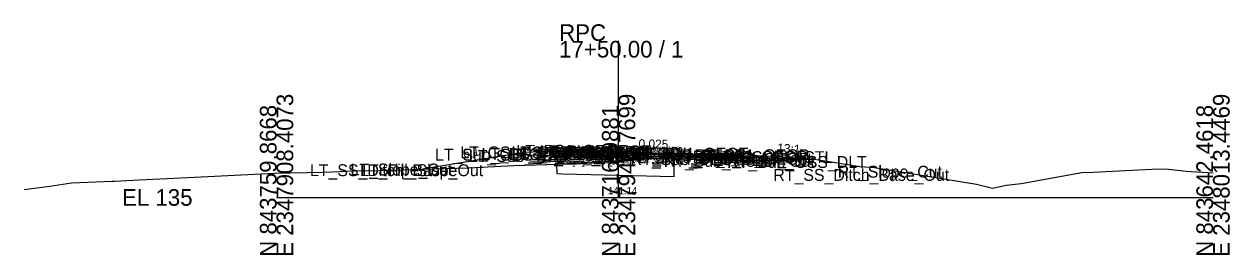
# Model space of a CAD drawing. Extents: x -26 to 203, y -10 to 7538.
# Drawn here: x 0 to 202.8, y 3990.3 to 4029.2 of the extents above; entities that cross this region are included whole.
import ezdxf

# ---------------------------------------------------------------- set-up
doc = ezdxf.new("R2010")
doc.units = 0
for name, color, linetype in [('Default', 7, 'Continuous'), ('Exist Cross Section Cell', 7, 'Continuous'), ('Exist XS Center Line Elevation Label', 7, 'Continuous'), ('Exist XS Ground Line', 7, 'Continuous'), ('Prop CMT Pvmt Course 1', 7, 'Continuous'), ('Prop CMT Pvmt Course 2', 7, 'Continuous'), ('Prop CMT Pvmt Course 3', 7, 'Continuous'), ('Prop CMT Pvmt Surface', 7, 'Continuous'), ('Prop CMT Pvmt Surface Shoulder', 7, 'Continuous'), ('Prop CMT Shld Paved Course 1', 7, 'Continuous'), ('Prop CMT Shld Paved Course 2', 7, 'Continuous'), ('Prop CMT Shld Paved Course 3', 7, 'Continuous'), ('Prop CMT Slope Grass', 7, 'Continuous'), ('Prop CMT Subgrade Earthwork', 7, 'Continuous'), ('Prop Road Sect_ Recs - UC (Outline)', 7, 'Continuous'), ('Prop XS Earthwork Shape', 7, 'Continuous'), ('Prop XS SE Text', 7, 'Continuous'), ('Prop XS Side Slope Text', 7, 'Continuous'), ('Scratch_Level_0', 7, 'Continuous')]:
    doc.layers.add(name, color=color, linetype=linetype)

msp = doc.modelspace()

# ---------------------------------------------------------------- linework, layer by layer
at = {"layer": 'Exist Cross Section Cell'}
for p, q in [((100, 4000), (100, 4026.39)), ((42.46, 4000), (100, 4000)), ((100, 4000), (200, 4000))]:
    msp.add_line(p, q, dxfattribs=at)
at = {"layer": 'Exist XS Ground Line'}
msp.add_lwpolyline([(0, 4001.35), (4.35, 4001.89), (7.96, 4002.46), (14.79, 4002.74), (15.27, 4002.76), (19.33, 4002.97), (28.68, 4003.44), (29.79, 4003.48), (42.1, 4004.07), (43.37, 4004.13), (44.78, 4004.17), (50.45, 4004.29), (55.52, 4004.46), (59.78, 4004.57), (68.94, 4004.8), (74.78, 4005.02), (82.36, 4005.37), (89.78, 4005.6), (92.94, 4005.67), (98.95, 4006.06), (100, 4006.14), (109.3, 4006.84), (110.35, 4006.89), (111.83, 4006.98), (112.49, 4006.99), (113.07, 4006.99), (113.65, 4006.98), (115.14, 4006.95), (115.87, 4006.94), (116.65, 4006.93), (118.51, 4006.89), (120.39, 4006.85), (121.19, 4006.84), (121.87, 4006.82), (124.18, 4006.76), (125.2, 4006.73), (126.45, 4006.69), (127.88, 4006.65), (128.57, 4006.63), (129.52, 4006.6), (131.75, 4006.5), (132.16, 4006.48), (132.88, 4006.44), (135.82, 4005.98), (140.61, 4005.21), (143.06, 4005.03), (160.23, 4002.25), (162.89, 4001.58), (165.18, 4002.05), (167.73, 4002.37), (177.93, 4004.18), (179.77, 4004.28), (189.71, 4004.77), (192.09, 4004.85), (195.51, 4004.45), (200, 4004.13)], dxfattribs=at)
at = {"layer": 'Prop CMT Pvmt Course 1'}
for p, q in [((100, 4007.67), (96, 4007.77)), ((96, 4007.77), (96, 4007.52)), ((96, 4007.52), (100, 4007.42)), ((100, 4007.42), (100, 4007.67)), ((100, 4007.67), (112, 4007.37)), ((100, 4007.42), (100, 4007.67)), ((100, 4007.42), (100, 4007.54)), ((100, 4007.54), (100, 4007.54)), ((100, 4007.54), (100, 4007.42)), ((100, 4007.42), (100, 4007.54)), ((100, 4007.54), (100, 4007.54)), ((100, 4007.54), (100, 4007.42)), ((100, 4007.42), (100, 4007.42)), ((112, 4007.12), (100, 4007.42)), ((100, 4007.42), (100, 4007.42)), ((112, 4007.37), (112, 4007.12))]:
    msp.add_line(p, q, dxfattribs=at)
at = {"layer": 'Prop CMT Pvmt Course 2'}
for p, q in [((100, 4007.42), (96, 4007.52)), ((96, 4007.52), (96, 4007.18)), ((96, 4007.18), (100, 4007.08)), ((100, 4007.08), (100, 4007.42)), ((100, 4007.08), (100, 4007.42)), ((100, 4007.42), (112, 4007.12)), ((112, 4006.78), (100, 4007.08)), ((112, 4007.12), (112, 4006.78))]:
    msp.add_line(p, q, dxfattribs=at)
at = {"layer": 'Prop CMT Pvmt Course 3'}
for p, q in [((100, 4007.08), (96, 4007.18)), ((96, 4007.18), (96, 4006.85)), ((96, 4006.85), (100, 4006.75)), ((100, 4006.75), (100, 4007.08)), ((100, 4007.08), (112, 4006.78)), ((100, 4006.75), (100, 4007.08)), ((112, 4006.45), (100, 4006.75)), ((112, 4006.78), (112, 4006.45))]:
    msp.add_line(p, q, dxfattribs=at)
at = {"layer": 'Prop CMT Pvmt Surface'}
for q in [(96, 4007.77), (112, 4007.37)]:
    msp.add_line((100, 4007.67), q, dxfattribs=at)
at = {"layer": 'Prop CMT Pvmt Surface Shoulder'}
for p, q in [((96, 4007.77), (92, 4007.87)), ((112, 4007.37), (122, 4007.12))]:
    msp.add_line(p, q, dxfattribs=at)
at = {"layer": 'Prop CMT Shld Paved Course 1'}
for p, q in [((92, 4007.87), (91.76, 4007.62)), ((91.76, 4007.62), (96, 4007.52)), ((96, 4007.77), (92, 4007.87)), ((96, 4007.52), (96, 4007.77)), ((112, 4007.37), (122, 4007.12)), ((112, 4007.12), (112, 4007.37)), ((122.26, 4006.86), (112, 4007.12)), ((122, 4007.12), (122.26, 4006.86))]:
    msp.add_line(p, q, dxfattribs=at)
at = {"layer": 'Prop CMT Shld Paved Course 2'}
for p, q in [((91.76, 4007.62), (91.43, 4007.3)), ((91.43, 4007.3), (96, 4007.18)), ((96, 4007.52), (91.76, 4007.62)), ((96, 4007.18), (96, 4007.52)), ((112, 4007.12), (122.26, 4006.86)), ((112, 4006.78), (112, 4007.12)), ((122.6, 4006.52), (112, 4006.78)), ((122.26, 4006.86), (122.6, 4006.52))]:
    msp.add_line(p, q, dxfattribs=at)
at = {"layer": 'Prop CMT Shld Paved Course 3'}
for p, q in [((90.93, 4007.31), (90.61, 4006.99)), ((90.61, 4006.99), (96, 4006.85)), ((91.43, 4007.3), (90.93, 4007.31)), ((96, 4007.18), (91.43, 4007.3)), ((96, 4006.85), (96, 4007.18)), ((112, 4006.78), (122.6, 4006.52)), ((112, 4006.45), (112, 4006.78)), ((123.44, 4006.16), (112, 4006.45)), ((122.6, 4006.52), (123.1, 4006.51)), ((123.1, 4006.51), (123.44, 4006.16))]:
    msp.add_line(p, q, dxfattribs=at)
at = {"layer": 'Prop CMT Slope Grass'}
for p, q in [((84, 4007.59), (66.99, 4004.75)), ((92, 4007.87), (84, 4007.59)), ((122, 4007.12), (126, 4006.98)), ((126, 4006.98), (132.88, 4006.44))]:
    msp.add_line(p, q, dxfattribs=at)
at = {"layer": 'Prop CMT Subgrade Earthwork'}
for p, q in [((90.61, 4006.99), (81.72, 4007.21)), ((96, 4006.85), (90.61, 4006.99)), ((100, 4006.75), (96, 4006.85)), ((100, 4006.75), (112, 4006.45)), ((112, 4006.45), (123.44, 4006.16)), ((123.44, 4006.16), (132.88, 4006.44))]:
    msp.add_line(p, q, dxfattribs=at)
at = {"layer": 'Prop Road Sect_ Recs - UC (Outline)'}
msp.add_lwpolyline([(109.34, 4003.52), (109.34, 4003.52), (109.34, 4006.55), (109.34, 4006.55), (109.34, 4006.53), (106, 4006.6), (92.94, 4005.67), (90.57, 4005.62), (89.57, 4005.6), (89.6, 4004.01), (90.61, 4003.99), (100, 4003.75)], close=True, dxfattribs=at)
at = {"layer": 'Prop XS Earthwork Shape'}
for points in [[(100, 4006.14), (106.07, 4006.6), (100, 4006.75), (96, 4006.85), (90.61, 4006.99), (81.72, 4007.21), (66.99, 4004.75), (68.94, 4004.8), (74.78, 4005.02), (82.36, 4005.37), (89.78, 4005.6), (92.94, 4005.67), (98.95, 4006.06)], [(109.3, 4006.84), (110.35, 4006.89), (111.83, 4006.98), (112.49, 4006.99), (113.07, 4006.99), (113.65, 4006.98), (115.14, 4006.95), (115.87, 4006.94), (116.65, 4006.93), (118.51, 4006.89), (120.39, 4006.85), (121.19, 4006.84), (121.87, 4006.82), (124.18, 4006.76), (125.2, 4006.73), (126.45, 4006.69), (127.88, 4006.65), (128.57, 4006.63), (129.52, 4006.6), (131.75, 4006.5), (132.16, 4006.48), (132.88, 4006.44), (123.44, 4006.16), (112, 4006.45), (106.07, 4006.6)]]:
    msp.add_lwpolyline(points, close=True, dxfattribs=at)

# ---------------------------------------------------------------- texts
at = {"layer": 'Default'}
msp.add_text('-', height=0.0001, dxfattribs=at).set_placement((42.46, 4000))
at = {"layer": 'Exist Cross Section Cell'}
for s, p in [('RPC', (90, 4026.39)), ('17+50.00 / 1', (90, 4023.59)), ('EL 135', (16.47, 3998.6))]:
    msp.add_text(s, height=2.8, dxfattribs=at).set_placement(p)
for s, p in [('E 2347908.4073', (45.27, 3990)), ('E 2347946.7699', (102.8, 3990)), ('E 2348013.4469', (202.8, 3990)), ('N 843759.8668', (42.46, 3990)), ('N 843716.9881', (100, 3990)), ('N 843642.4618', (200, 3990))]:
    msp.add_text(s, height=2.8, rotation=90, dxfattribs=at).set_placement(p)
at = {"layer": 'Exist XS Center Line Elevation Label'}
msp.add_text('141.14', height=1.2, dxfattribs=at).set_placement((98.23, 4000.54))
at = {"layer": 'Prop XS SE Text'}
msp.add_text('0.025', height=1.5, rotation=358.5679, dxfattribs=at).set_placement((103.34, 4008.33))
at = {"layer": 'Prop XS Side Slope Text'}
for s, rotation, p in [('6:1', 9.4623, (73.93, 4006.65)), ('13:1', 355.5761, (126.64, 4007.64))]:
    msp.add_text(s, height=1.5, rotation=rotation, dxfattribs=at).set_placement(p)
at = {"layer": 'Scratch_Level_0'}
for s, p in [('LT_Sub_OSS_DLT', (69.12, 4006.21)), ('LT_GS_OS_CTL', (73.37, 4006.59)), ('LT_PS3_Shelf_Out', (76.92, 4006.31)), ('LT_PS3_OEOP', (81.67, 4006.3)), ('LT_PS2_OEOP', (81.99, 4006.62)), ('LT_PS1_OEOP', (82.8, 4006.87)), ('LT_PV2_OEOT', (86.17, 4006.52)), ('LT_PV3_OEOT', (86.17, 4006.18)), ('LT_PV1_OEOT', (86.74, 4006.77)), ('RT_PV2_OEEOP', (89.26, 4006.42)), ('LT_PV2_OEEOP', (89.31, 4006.42)), ('RT_PV1_OEEOP', (89.83, 4006.54)), ('LT_PV1_OEEOP', (89.87, 4006.54)), ('RT_PV2_IEEOP', (89.91, 4006.42)), ('LT_PV2_IEEOP', (89.95, 4006.42)), ('RT_PV1_IEEOP', (90.47, 4006.54)), ('LT_PV1_IEEOP', (90.52, 4006.54)), ('PV2_PGL', (93.91, 4006.42)), ('PV1_PGL', (94.47, 4006.67)), ('RT_PV2_OEOT', (102.13, 4006.12)), ('RT_PV1_OEOT', (102.69, 4006.37)), ('RT_PS1_OEOP', (112.76, 4006.12)), ('LT_Sub_Trench_Out', (74.81, 4005.99)), ('LT_Sub_OEOT', (86.08, 4005.85)), ('RT_Sub_OEEOP', (89.17, 4005.75)), ('LT_Sub_OEEOP', (89.21, 4005.75)), ('RT_PV3_OEEOP', (89.26, 4006.08)), ('LT_PV3_OEEOP', (89.31, 4006.08)), ('RT_Sub_OEOT', (102.03, 4005.45)), ('RT_PV3_OEOT', (102.13, 4005.78)), ('RT_Sub_Trench_Out', (107.6, 4005.16)), ('RT_PS3_Shelf_Out', (109.04, 4005.51)), ('RT_PS2_OEOP', (112.45, 4005.86)), ('RT_PS3_OEOP', (112.79, 4005.52)), ('RT_GS_OS_CTL', (115.32, 4005.8)), ('RT_Sub_OSS_DLT', (118.27, 4004.98)), ('LT_SS_Ditch_Base_Out', (48.08, 4003.59)), ('LT_Slope_Cut', (54.91, 4003.71)), ('LT_Fill_Slope', (56.52, 4003.59)), ('RT_SS_Ditch_Base_Out', (126.03, 4002.8)), ('RT_Slope_Cut', (136.87, 4003.34))]:
    msp.add_text(s, height=2, dxfattribs=at).set_placement(p)

doc.saveas('drawing.dxf')
